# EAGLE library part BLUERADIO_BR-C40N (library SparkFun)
Bluetooth SMD Module BR-C40A with antenna cut off. 50 Ohm antenna trace and connector required. Footprint fully proven. Spark Fun Electronics SKU : RF-BT-SMD
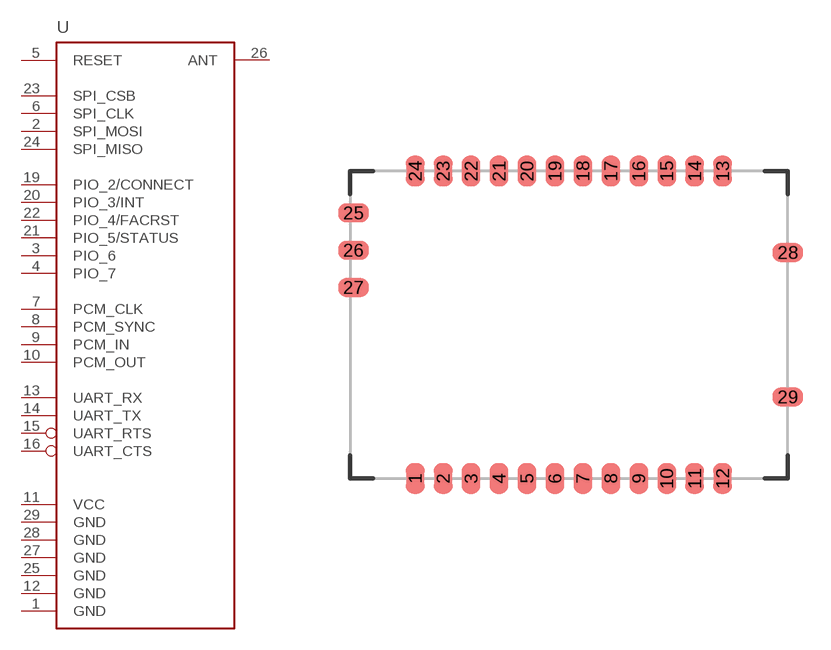
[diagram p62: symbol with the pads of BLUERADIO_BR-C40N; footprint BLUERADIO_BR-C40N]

Designator prefix -

## BLUERADIO_BR-C40N  [BLUERADIO_BR-C40N]
1  GND  pwr
2  SPI_MOSI
3  PIO_6
4  PIO_7
5  RESET
6  SPI_CLK
7  PCM_CLK
8  PCM_SYNC
9  PCM_IN
10  PCM_OUT
11  VCC
12  GND  pwr
13  UART_RX  in
14  UART_TX  out
15  UART_RTS  out
16  UART_CTS  in
19  PIO_2/CONNECT  out
20  PIO_3/INT  in
21  PIO_5/STATUS  out
22  PIO_4/FACRST
23  SPI_CSB
24  SPI_MISO
25  GND  pwr
26  ANT
27  GND  pwr
28  GND  pwr
29  GND  pwr

## Footprint BLUERADIO_BR-C40N (pad centres in mm)
smd 0.8 x 1.3: 1 -6.6,-6.6; 2 -5.4,-6.6; 3 -4.2,-6.6; 4 -3,-6.6; 5 -1.8,-6.6; 6 -0.6,-6.6; 7 0.6,-6.6; 8 1.8,-6.6; 9 3,-6.6; 10 4.2,-6.6; 11 5.4,-6.6; 12 6.6,-6.6; 13 6.6,6.6; 14 5.4,6.6; 15 4.2,6.6; 16 3,6.6; 17 1.8,6.6; 18 0.6,6.6; 19 -0.6,6.6; 20 -1.8,6.6; 21 -3,6.6; 22 -4.2,6.6; 23 -5.4,6.6; 24 -6.6,6.6
smd 1.3 x 0.8: 25 -9.25,4.8; 26 -9.25,3.2; 27 -9.25,1.6; 28 9.4,3.1; 29 9.4,-3.1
